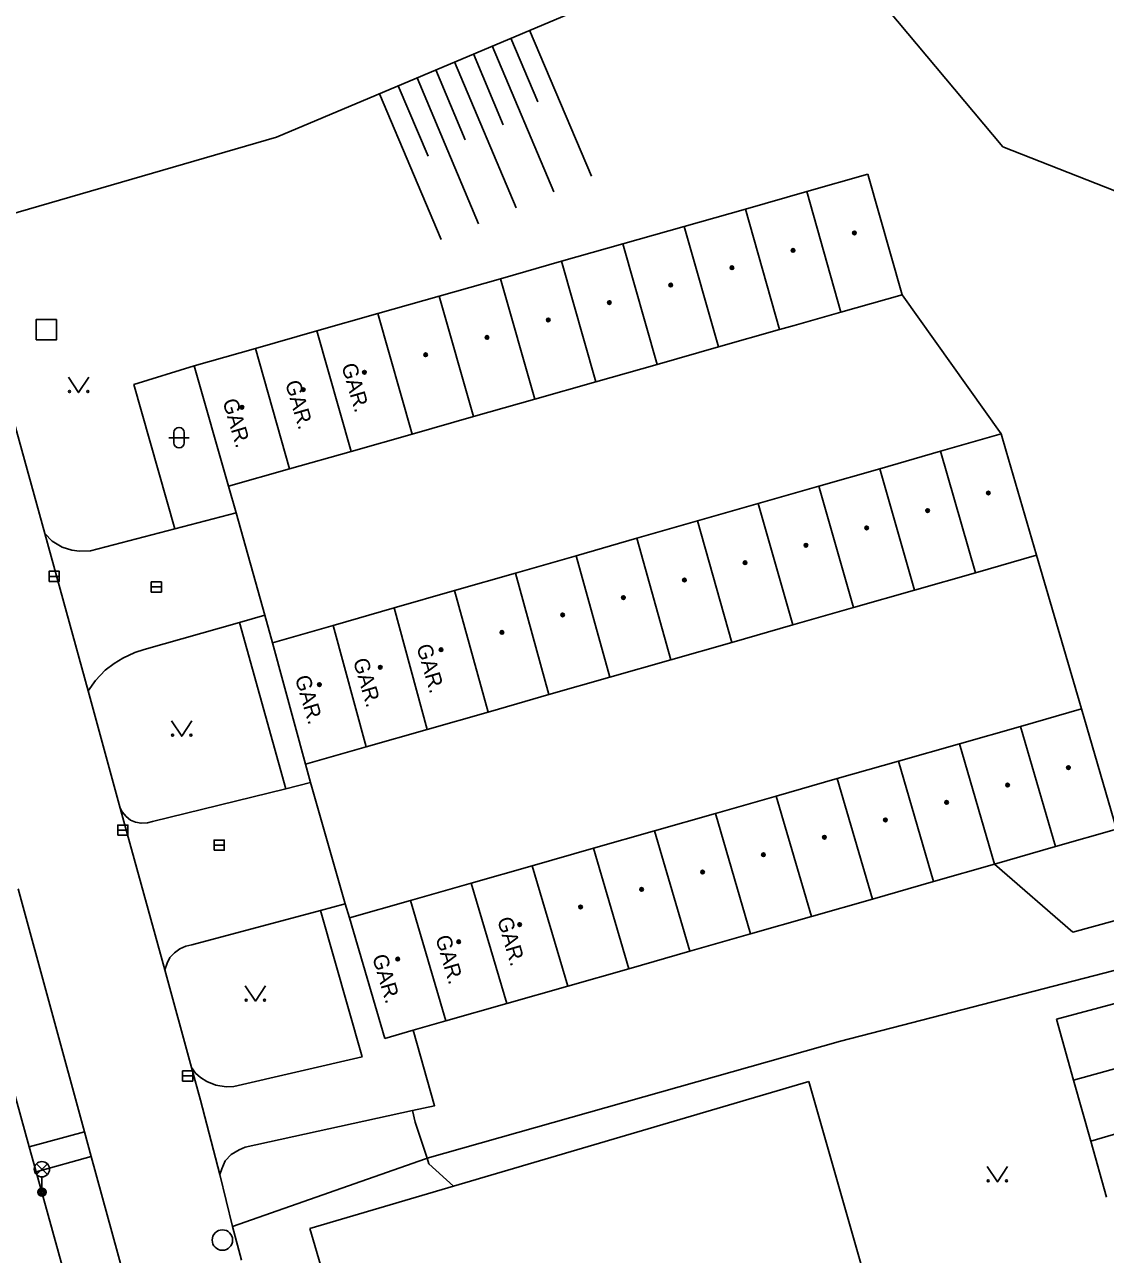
# Model space of a CAD drawing. Extents: x -595546 to -593986, y -1160845 to -1159202.
# Drawn here: x -595295.1 to -595242.1, y -1160217.4 to -1160157.1 of the extents above; entities that cross this region are included whole.
import ezdxf

# ---------------------------------------------------------------- set-up
doc = ezdxf.new("R2010")
doc.units = 0
for name, color, linetype in [('Level 26', 7, 'Continuous'), ('Level 27', 7, 'Continuous'), ('Level 33', 7, 'Continuous'), ('Level 36', 7, 'Continuous'), ('Level 39', 7, 'Continuous'), ('Specificka linie pasportu komunikaci', 7, 'Continuous'), ('TM - budovy zdene_ betonove - VP', 7, 'Continuous'), ('TM - chodniky - VP', 7, 'Continuous'), ('TM - horni hrana svahu', 7, 'Continuous'), ('TM - komunikace - VP', 7, 'Continuous'), ('TM - plot drateny_ kovovy - VP', 7, 'Continuous'), ('TM - pomocna konstrukcni linie', 7, 'Continuous'), ('TM - popis objektu', 7, 'Continuous'), ('TM - rozhrani ploch obecne - VP', 7, 'Continuous'), ('TM - srafovani', 7, 'Continuous')]:
    doc.layers.add(name, color=color, linetype=linetype)

msp = doc.modelspace()

# ---------------------------------------------------------------- linework, layer by layer
at = {"layer": 'Level 26'}
msp.add_lwpolyline([(-595294.52, -1160172.54), (-595293.52, -1160172.54), (-595293.52, -1160171.54), (-595294.52, -1160171.54)], close=True, dxfattribs=at)
at = {"layer": 'Level 27'}
for p, q in [((-595293.88, -1160184.14), (-595293.38, -1160184.14)), ((-595288.87, -1160184.66), (-595288.37, -1160184.66)), ((-595290.51, -1160196.59), (-595290.01, -1160196.59)), ((-595285.79, -1160197.33), (-595285.29, -1160197.33)), ((-595287.33, -1160208.65), (-595286.83, -1160208.65))]:
    msp.add_line(p, q, dxfattribs=at)
for points in [[(-595293.88, -1160184.39), (-595293.38, -1160184.39), (-595293.38, -1160183.89), (-595293.88, -1160183.89)], [(-595288.87, -1160184.91), (-595288.37, -1160184.91), (-595288.37, -1160184.41), (-595288.87, -1160184.41)], [(-595290.51, -1160196.84), (-595290.01, -1160196.84), (-595290.01, -1160196.34), (-595290.51, -1160196.34)], [(-595285.79, -1160197.58), (-595285.29, -1160197.58), (-595285.29, -1160197.08), (-595285.79, -1160197.08)], [(-595287.33, -1160208.9), (-595286.83, -1160208.9), (-595286.83, -1160208.4), (-595287.33, -1160208.4)]]:
    msp.add_lwpolyline(points, close=True, dxfattribs=at)
msp.add_circle((-595285.38, -1160216.7), 0.5, dxfattribs=at)
at = {"layer": 'Level 33'}
for p, q in [((-595294.495, -1160213.49), (-595293.965, -1160212.96)), ((-595294.495, -1160212.96), (-595293.965, -1160213.49)), ((-595294.23, -1160213.6), (-595294.23, -1160214.35))]:
    msp.add_line(p, q, dxfattribs=at)
for centre, radius in [((-595294.23, -1160213.225), 0.375), ((-595294.23, -1160214.35), 0.2), ((-595294.23, -1160214.35), 0.145), ((-595294.23, -1160214.35), 0.0876)]:
    msp.add_circle(centre, radius, dxfattribs=at)
at = {"layer": 'Level 36'}
for p, q in [((-595287.756, -1160177.086), (-595287.756, -1160177.586)), ((-595287.256, -1160177.086), (-595287.256, -1160177.586)), ((-595288.006, -1160177.336), (-595287.006, -1160177.336))]:
    msp.add_line(p, q, dxfattribs=at)
for points in [[(-595292.93, -1160174.37), (-595292.43, -1160175.12), (-595291.93, -1160174.37)], [(-595287.87, -1160191.23), (-595287.37, -1160191.98), (-595286.87, -1160191.23)], [(-595284.26, -1160204.23), (-595283.76, -1160204.98), (-595283.26, -1160204.23)], [(-595247.87, -1160213.1), (-595247.37, -1160213.85), (-595246.87, -1160213.1)]]:
    msp.add_lwpolyline(points, dxfattribs=at)
for centre in [(-595292.88, -1160175.07), (-595291.981, -1160175.07), (-595287.82, -1160191.93), (-595286.921, -1160191.93), (-595284.21, -1160204.93), (-595283.311, -1160204.93), (-595247.82, -1160213.8), (-595246.921, -1160213.8)]:
    msp.add_circle(centre, 0.05, dxfattribs=at)
for centre, start, end in [((-595287.506, -1160177.086), 0, 180), ((-595287.506, -1160177.586), 180, 0)]:
    msp.add_arc(centre, 0.25, start, end, dxfattribs=at)
at = {"layer": 'Level 39'}
for centre, radius in [((-595254.38, -1160167.29), 0.09), ((-595254.38, -1160167.29), 0.0398), ((-595257.39, -1160168.15), 0.09), ((-595257.39, -1160168.15), 0.0398), ((-595260.39, -1160169), 0.09), ((-595260.39, -1160169), 0.0398), ((-595263.39, -1160169.85), 0.09), ((-595263.39, -1160169.85), 0.0398), ((-595266.4, -1160170.71), 0.09), ((-595266.4, -1160170.71), 0.0398), ((-595269.4, -1160171.56), 0.09), ((-595269.4, -1160171.56), 0.0398), ((-595272.4, -1160172.42), 0.09), ((-595272.4, -1160172.42), 0.0398), ((-595275.41, -1160173.27), 0.09), ((-595275.41, -1160173.27), 0.0398), ((-595278.41, -1160174.13), 0.09), ((-595278.41, -1160174.13), 0.0398), ((-595281.41, -1160174.98), 0.09), ((-595281.41, -1160174.98), 0.0398), ((-595284.42, -1160175.84), 0.09), ((-595284.42, -1160175.84), 0.0398), ((-595247.81, -1160180.05), 0.09), ((-595247.81, -1160180.05), 0.0398), ((-595250.79, -1160180.91), 0.09), ((-595250.79, -1160180.91), 0.0398), ((-595253.78, -1160181.76), 0.09), ((-595253.78, -1160181.76), 0.0398), ((-595256.76, -1160182.61), 0.09), ((-595256.76, -1160182.61), 0.0398), ((-595259.74, -1160183.47), 0.09), ((-595259.74, -1160183.47), 0.0398), ((-595262.72, -1160184.32), 0.09), ((-595262.72, -1160184.32), 0.0398), ((-595265.71, -1160185.18), 0.09), ((-595265.71, -1160185.18), 0.0398), ((-595268.69, -1160186.03), 0.09), ((-595268.69, -1160186.03), 0.0398), ((-595271.67, -1160186.89), 0.09), ((-595271.67, -1160186.89), 0.0398), ((-595274.65, -1160187.74), 0.09), ((-595274.65, -1160187.74), 0.0398), ((-595277.64, -1160188.6), 0.09), ((-595277.64, -1160188.6), 0.0398), ((-595280.62, -1160189.45), 0.09), ((-595280.62, -1160189.45), 0.0398), ((-595243.88, -1160193.52), 0.09), ((-595243.88, -1160193.52), 0.0398), ((-595246.87, -1160194.38), 0.09), ((-595246.87, -1160194.38), 0.0398), ((-595249.86, -1160195.23), 0.09), ((-595249.86, -1160195.23), 0.0398), ((-595252.86, -1160196.09), 0.09), ((-595252.86, -1160196.09), 0.0398), ((-595255.85, -1160196.94), 0.09), ((-595255.85, -1160196.94), 0.0398), ((-595258.84, -1160197.8), 0.09), ((-595258.84, -1160197.8), 0.0398), ((-595261.83, -1160198.65), 0.09), ((-595261.83, -1160198.65), 0.0398), ((-595264.82, -1160199.5), 0.09), ((-595264.82, -1160199.5), 0.0398), ((-595267.81, -1160200.36), 0.09), ((-595267.81, -1160200.36), 0.0398), ((-595270.8, -1160201.22), 0.09), ((-595270.8, -1160201.22), 0.0398), ((-595273.79, -1160202.07), 0.09), ((-595273.79, -1160202.07), 0.0398), ((-595276.78, -1160202.92), 0.09), ((-595276.78, -1160202.92), 0.0398)]:
    msp.add_circle(centre, radius, dxfattribs=at)
at = {"layer": 'Specificka linie pasportu komunikaci'}
for points in [[(-595276.06, -1160210.35), (-595275.93, -1160210.92), (-595275.34, -1160212.69)], [(-595292.14, -1160211.39), (-595294.86, -1160212.12)], [(-595294.51, -1160213.35), (-595291.81, -1160212.6)], [(-595275.34, -1160212.69), (-595275.25, -1160212.96), (-595274.05, -1160214.06)]]:
    msp.add_lwpolyline(points, dxfattribs=at)
at = {"layer": 'TM - budovy zdene_ betonove - VP'}
for points in [[(-595256.72, -1160165.26), (-595253.72, -1160164.41)], [(-595253.72, -1160164.41), (-595252.04, -1160170.32)], [(-595259.73, -1160166.12), (-595256.72, -1160165.26)], [(-595256.72, -1160165.26), (-595255.04, -1160171.18)], [(-595262.73, -1160166.97), (-595259.73, -1160166.12)], [(-595258.05, -1160172.03), (-595259.73, -1160166.12)], [(-595265.74, -1160167.83), (-595262.73, -1160166.97)], [(-595261.05, -1160172.88), (-595262.73, -1160166.97)], [(-595268.74, -1160168.68), (-595265.74, -1160167.83)], [(-595264.06, -1160173.74), (-595265.74, -1160167.83)], [(-595271.74, -1160169.54), (-595268.74, -1160168.68)], [(-595267.06, -1160174.59), (-595268.74, -1160168.68)], [(-595274.75, -1160170.39), (-595271.74, -1160169.54)], [(-595270.06, -1160175.45), (-595271.74, -1160169.54)], [(-595277.75, -1160171.24), (-595274.75, -1160170.39)], [(-595273.07, -1160176.3), (-595274.75, -1160170.39)], [(-595252.04, -1160170.32), (-595255.04, -1160171.18)], [(-595280.75, -1160172.1), (-595277.75, -1160171.24)], [(-595276.07, -1160177.16), (-595277.75, -1160171.24)], [(-595255.04, -1160171.18), (-595257.34, -1160171.83)], [(-595283.76, -1160172.96), (-595280.75, -1160172.1)], [(-595279.07, -1160178.01), (-595280.75, -1160172.1)], [(-595258.05, -1160172.03), (-595261.05, -1160172.88)], [(-595257.34, -1160171.83), (-595258.05, -1160172.03)], [(-595261.05, -1160172.88), (-595264.06, -1160173.74)], [(-595286.76, -1160173.81), (-595283.76, -1160172.96)], [(-595282.08, -1160178.87), (-595283.76, -1160172.96)], [(-595285.08, -1160179.72), (-595286.76, -1160173.81)], [(-595264.06, -1160173.74), (-595267.06, -1160174.59)], [(-595267.06, -1160174.59), (-595270.06, -1160175.45)], [(-595270.06, -1160175.45), (-595273.07, -1160176.3)], [(-595273.07, -1160176.3), (-595276.07, -1160177.16)], [(-595276.07, -1160177.16), (-595279.07, -1160178.01)], [(-595247.19, -1160177.15), (-595250.16, -1160178)], [(-595246.94, -1160178), (-595247.19, -1160177.15)], [(-595279.07, -1160178.01), (-595282.08, -1160178.87)], [(-595253.14, -1160178.86), (-595250.16, -1160178)], [(-595250.16, -1160178), (-595248.44, -1160183.96)], [(-595246.94, -1160178), (-595245.45, -1160183.1)], [(-595282.08, -1160178.87), (-595285.08, -1160179.72)], [(-595256.12, -1160179.71), (-595253.14, -1160178.86)], [(-595253.14, -1160178.86), (-595251.43, -1160184.81)], [(-595259.1, -1160180.56), (-595256.12, -1160179.71)], [(-595256.12, -1160179.71), (-595254.42, -1160185.66)], [(-595262.08, -1160181.42), (-595259.1, -1160180.56)], [(-595259.1, -1160180.56), (-595257.4, -1160186.52)], [(-595265.05, -1160182.27), (-595262.08, -1160181.42)], [(-595262.08, -1160181.42), (-595260.39, -1160187.38)], [(-595268.03, -1160183.13), (-595265.05, -1160182.27)], [(-595265.05, -1160182.27), (-595263.38, -1160188.23)], [(-595271.01, -1160183.98), (-595268.03, -1160183.13)], [(-595268.03, -1160183.13), (-595266.37, -1160189.08)], [(-595245.45, -1160183.1), (-595248.44, -1160183.96)], [(-595273.99, -1160184.84), (-595271.01, -1160183.98)], [(-595271.01, -1160183.98), (-595269.36, -1160189.94)], [(-595248.44, -1160183.96), (-595251.43, -1160184.81)], [(-595276.96, -1160185.69), (-595273.99, -1160184.84)], [(-595272.34, -1160190.8), (-595273.99, -1160184.84)], [(-595254.42, -1160185.66), (-595251.43, -1160184.81)], [(-595279.94, -1160186.55), (-595276.96, -1160185.69)], [(-595275.33, -1160191.65), (-595276.96, -1160185.69)], [(-595254.42, -1160185.66), (-595257.4, -1160186.52)], [(-595279.94, -1160186.55), (-595282.92, -1160187.4)], [(-595278.32, -1160192.5), (-595279.94, -1160186.55)], [(-595257.4, -1160186.52), (-595260.39, -1160187.38)], [(-595260.39, -1160187.38), (-595263.38, -1160188.23)], [(-595282.92, -1160187.4), (-595281.31, -1160193.36)], [(-595263.38, -1160188.23), (-595266.37, -1160189.08)], [(-595266.37, -1160189.08), (-595269.36, -1160189.94)], [(-595272.34, -1160190.8), (-595270.93, -1160190.39)], [(-595270.93, -1160190.39), (-595269.36, -1160189.94)], [(-595272.34, -1160190.8), (-595275.33, -1160191.65)], [(-595246.24, -1160191.5), (-595243.25, -1160190.64)], [(-595241.53, -1160196.54), (-595243.25, -1160190.64)], [(-595249.23, -1160192.35), (-595246.24, -1160191.5)], [(-595244.52, -1160197.4), (-595246.24, -1160191.5)], [(-595275.33, -1160191.65), (-595278.32, -1160192.5)], [(-595281.31, -1160193.36), (-595278.32, -1160192.5)], [(-595252.22, -1160193.2), (-595249.23, -1160192.35)], [(-595249.23, -1160192.35), (-595247.51, -1160198.26)], [(-595255.22, -1160194.06), (-595252.22, -1160193.2)], [(-595250.5, -1160199.11), (-595252.22, -1160193.2)], [(-595258.21, -1160194.92), (-595255.22, -1160194.06)], [(-595253.49, -1160199.97), (-595255.22, -1160194.06)], [(-595261.2, -1160195.77), (-595258.21, -1160194.92)], [(-595256.48, -1160200.82), (-595258.21, -1160194.92)], [(-595264.19, -1160196.62), (-595261.2, -1160195.77)], [(-595259.47, -1160201.68), (-595261.2, -1160195.77)], [(-595267.18, -1160197.48), (-595264.19, -1160196.62)], [(-595262.46, -1160202.53), (-595264.19, -1160196.62)], [(-595244.52, -1160197.4), (-595241.53, -1160196.54)], [(-595270.18, -1160198.34), (-595267.18, -1160197.48)], [(-595265.45, -1160203.39), (-595267.18, -1160197.48)], [(-595244.52, -1160197.4), (-595247.51, -1160198.26)], [(-595273.17, -1160199.19), (-595270.18, -1160198.34)], [(-595268.44, -1160204.24), (-595270.18, -1160198.34)], [(-595247.51, -1160198.26), (-595250.5, -1160199.11)], [(-595276.16, -1160200.04), (-595273.17, -1160199.19)], [(-595271.43, -1160205.1), (-595273.17, -1160199.19)], [(-595250.5, -1160199.11), (-595253.49, -1160199.97)], [(-595276.16, -1160200.04), (-595279.15, -1160200.9)], [(-595274.42, -1160205.95), (-595276.16, -1160200.04)], [(-595253.49, -1160199.97), (-595256.48, -1160200.82)], [(-595279.15, -1160200.9), (-595277.41, -1160206.81)], [(-595256.48, -1160200.82), (-595259.47, -1160201.68)], [(-595259.47, -1160201.68), (-595262.46, -1160202.53)], [(-595262.46, -1160202.53), (-595265.45, -1160203.39)], [(-595265.45, -1160203.39), (-595268.44, -1160204.24)], [(-595268.44, -1160204.24), (-595271.43, -1160205.1)], [(-595244.47, -1160205.86), (-595238.49, -1160204.26)], [(-595271.43, -1160205.1), (-595274.42, -1160205.95)], [(-595274.42, -1160205.95), (-595276.03, -1160206.41)], [(-595243.64, -1160208.85), (-595244.47, -1160205.86)], [(-595276.03, -1160206.41), (-595277.41, -1160206.81)], [(-595237.66, -1160207.2), (-595243.64, -1160208.85)], [(-595256.62, -1160208.92), (-595274.05, -1160214.06)], [(-595252.83, -1160222.2), (-595256.62, -1160208.92)], [(-595242.79, -1160211.85), (-595243.64, -1160208.85)], [(-595236.84, -1160210.1), (-595242.79, -1160211.85)], [(-595242.02, -1160214.59), (-595242.79, -1160211.85)], [(-595274.05, -1160214.06), (-595281.09, -1160216.13)], [(-595281.09, -1160216.13), (-595280.49, -1160218.2)]]:
    msp.add_lwpolyline(points, dxfattribs=at)
at = {"layer": 'TM - chodniky - VP'}
for points in [[(-595247.19, -1160177.15), (-595252.04, -1160170.32)], [(-595285.08, -1160179.72), (-595284.71, -1160181.03)], [(-595284.71, -1160181.03), (-595287.71, -1160181.81)], [(-595287.71, -1160181.81), (-595291.85, -1160182.89)], [(-595294.08, -1160182.04), (-595293.72, -1160182.41), (-595293.24, -1160182.7), (-595292.77, -1160182.85), (-595292.39, -1160182.91), (-595291.85, -1160182.89)], [(-595243.25, -1160190.64), (-595245.45, -1160183.1)], [(-595283.3, -1160186.05), (-595284.54, -1160186.4)], [(-595283.3, -1160186.05), (-595282.92, -1160187.4)], [(-595284.54, -1160186.4), (-595289.22, -1160187.72)], [(-595291.96, -1160189.76), (-595291.61, -1160189.25), (-595291.13, -1160188.75), (-595290.69, -1160188.42), (-595290.26, -1160188.15), (-595289.68, -1160187.88), (-595289.22, -1160187.72)], [(-595281.31, -1160193.36), (-595281.05, -1160194.26)], [(-595282.26, -1160194.56), (-595288.8, -1160196.17)], [(-595281.05, -1160194.26), (-595282.26, -1160194.56)], [(-595288.8, -1160196.17), (-595289.06, -1160196.24), (-595289.37, -1160196.25), (-595289.64, -1160196.2), (-595289.89, -1160196.1), (-595290.1, -1160195.92), (-595290.29, -1160195.7), (-595290.39, -1160195.51)], [(-595294.86, -1160212.12), (-595298.15, -1160200.23)], [(-595280.56, -1160200.53), (-595286.87, -1160202.22)], [(-595280.56, -1160200.53), (-595278.53, -1160207.72), (-595284.81, -1160209.17)], [(-595279.35, -1160200.21), (-595280.56, -1160200.53)], [(-595279.35, -1160200.21), (-595279.15, -1160200.9)], [(-595286.87, -1160202.22), (-595287.17, -1160202.29), (-595287.46, -1160202.42), (-595287.72, -1160202.61), (-595287.96, -1160202.84), (-595288.08, -1160203.11), (-595288.21, -1160203.44)], [(-595276.03, -1160206.41), (-595274.97, -1160210.11), (-595276.06, -1160210.35)], [(-595284.81, -1160209.17), (-595285.2, -1160209.19), (-595285.7, -1160209.11), (-595286.15, -1160208.92), (-595286.45, -1160208.72), (-595286.7, -1160208.51), (-595286.9, -1160208.24)], [(-595276.06, -1160210.35), (-595284.26, -1160212.15)], [(-595294.51, -1160213.35), (-595294.86, -1160212.12)], [(-595284.26, -1160212.15), (-595284.56, -1160212.28), (-595284.95, -1160212.51), (-595285.24, -1160212.82), (-595285.41, -1160213.21), (-595285.5, -1160213.49)], [(-595287.56, -1160238.46), (-595294.51, -1160213.35)]]:
    msp.add_lwpolyline(points, dxfattribs=at)
at = {"layer": 'TM - horni hrana svahu'}
for points in [[(-595282.73, -1160162.59), (-595258.6, -1160152.4)], [(-595298.46, -1160167.16), (-595282.73, -1160162.59)], [(-595227.26, -1160194.68), (-595228.29, -1160197.37), (-595243.67, -1160201.6)]]:
    msp.add_lwpolyline(points, dxfattribs=at)
at = {"layer": 'TM - komunikace - VP'}
for points in [[(-595294.08, -1160182.04), (-595297.01, -1160171.49)], [(-595291.96, -1160189.76), (-595294.08, -1160182.04)], [(-595290.39, -1160195.51), (-595291.96, -1160189.76)], [(-595288.21, -1160203.44), (-595290.39, -1160195.51)], [(-595295.4, -1160199.47), (-595292.14, -1160211.39)], [(-595286.9, -1160208.24), (-595288.21, -1160203.44)], [(-595286.46, -1160209.84), (-595286.9, -1160208.24)], [(-595285.5, -1160213.49), (-595286.46, -1160209.84)], [(-595292.14, -1160211.39), (-595291.81, -1160212.6)], [(-595291.81, -1160212.6), (-595284.47, -1160239.38)], [(-595284.88, -1160216.03), (-595285.5, -1160213.49)], [(-595284.44, -1160217.68), (-595284.88, -1160216.03)]]:
    msp.add_lwpolyline(points, dxfattribs=at)
at = {"layer": 'TM - plot drateny_ kovovy - VP'}
for points in [[(-595247.1, -1160163.06), (-595253.2, -1160155.78)], [(-595236.49, -1160167.24), (-595247.1, -1160163.06)], [(-595255.07, -1160206.94), (-595238.66, -1160202.7)], [(-595275.34, -1160212.69), (-595255.07, -1160206.94)], [(-595275.42, -1160212.71), (-595275.34, -1160212.69)]]:
    msp.add_lwpolyline(points, dxfattribs=at)
at = {"layer": 'TM - pomocna konstrukcni linie'}
msp.add_lwpolyline([(-595243.67, -1160201.6), (-595247.51, -1160198.26)], dxfattribs=at)
at = {"layer": 'TM - rozhrani ploch obecne - VP'}
for points in [[(-595286.76, -1160173.81), (-595289.72, -1160174.73), (-595287.71, -1160181.81)], [(-595284.71, -1160181.03), (-595283.3, -1160186.05)], [(-595284.54, -1160186.4), (-595282.26, -1160194.56)], [(-595281.05, -1160194.26), (-595279.35, -1160200.21)], [(-595275.42, -1160212.71), (-595284.88, -1160216.03)]]:
    msp.add_lwpolyline(points, dxfattribs=at)
at = {"layer": 'TM - srafovani'}
for points in [[(-595271.23, -1160157.73), (-595269.91, -1160160.86)], [(-595270.31, -1160157.34), (-595267.28, -1160164.51)], [(-595272.15, -1160158.12), (-595269.12, -1160165.28)], [(-595273.99, -1160158.9), (-595270.97, -1160166.06)], [(-595273.07, -1160158.51), (-595271.6, -1160161.99)], [(-595274.91, -1160159.29), (-595273.47, -1160162.72)], [(-595276.76, -1160160.07), (-595275.29, -1160163.53)], [(-595275.83, -1160159.68), (-595272.81, -1160166.84)], [(-595277.68, -1160160.46), (-595274.65, -1160167.62)]]:
    msp.add_lwpolyline(points, dxfattribs=at)

# ---------------------------------------------------------------- texts
at = {"layer": 'TM - popis objektu'}
for p in [(-595279.55, -1160173.8), (-595282.31, -1160174.64), (-595285.38, -1160175.54), (-595275.87, -1160187.58), (-595278.98, -1160188.27), (-595281.83, -1160189.11), (-595271.91, -1160200.97), (-595274.94, -1160201.86), (-595278.04, -1160202.8)]:
    msp.add_text('GAR.', height=0.75, rotation=286.37, dxfattribs=at).set_placement(p)

doc.saveas('drawing.dxf')
